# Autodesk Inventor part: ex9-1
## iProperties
Shininess: 64.0
Length Units: 11272
Angle Units: 11279
Time Units: 11290
Mass Units: 11286
Length Display Precision: 3
Angle Display Precision: 2
Compacted: True
Part Number: ex9-1
Document SubType Name: Sheet Metal
Created: 2002-11
Designer: Elise Moss
Density: 0.0
Volumn: 0.0
Area: 0.0
PropertySet Name: Model Information
Control State: 0
Master: False
Checked Out: False
Author: Elise Moss
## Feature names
1. Plate1
2. Bend1
